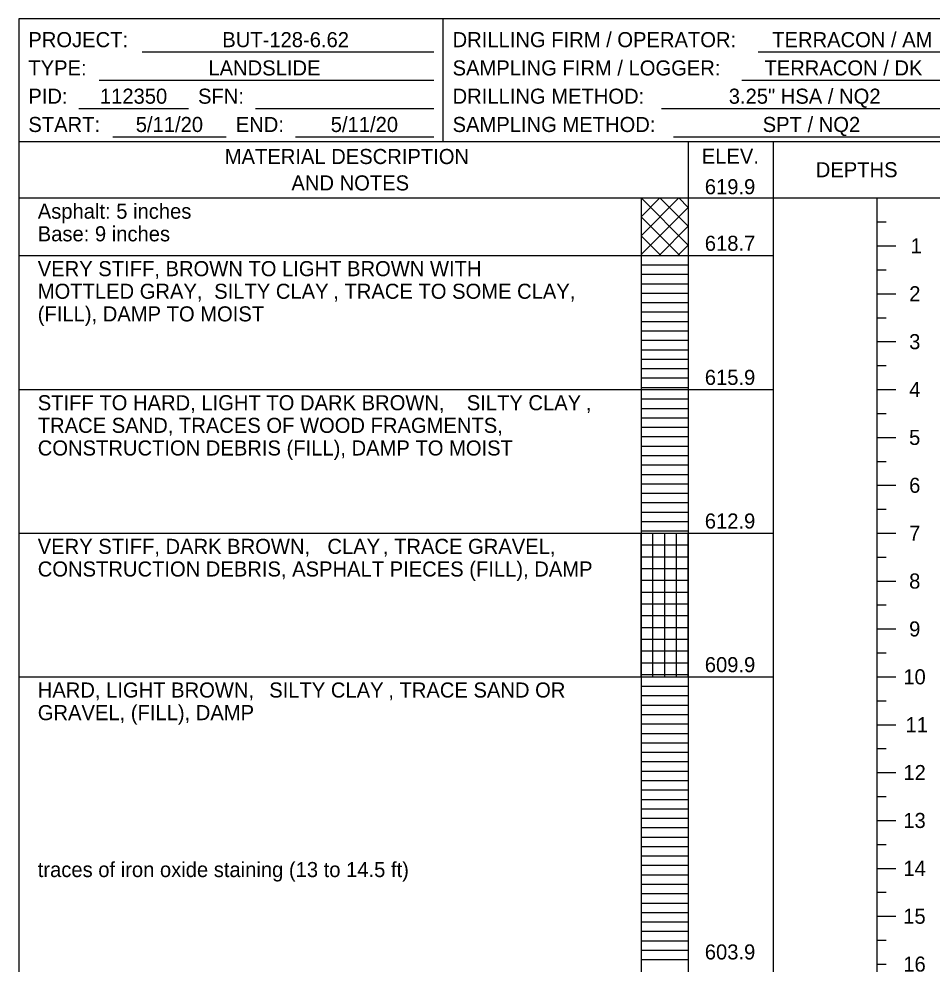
# Model space of a CAD drawing. Extents: x 0 to 0.833, y -0.32 to 0.608.
# Drawn here: x 0 to 0.4036, y 0.1905 to 0.6083 of the extents above; entities that cross this region are included whole.
import ezdxf

# ---------------------------------------------------------------- set-up
doc = ezdxf.new("R2010")
doc.units = 0

msp = doc.modelspace()

# ---------------------------------------------------------------- linework, layer by layer
msp.add_lwpolyline([(0, -0.32004), (0.83333, -0.32004), (0.83333, 0.60833), (0, 0.60833)], close=True)
for points in [[(0.1875, 0.55417), (0.1875, 0.60833)], [(0.05444, 0.59375), (0.18333, 0.59375)], [(0.32667, 0.59375), (0.4125, 0.59375)], [(0.03542, 0.58125), (0.18333, 0.58125)], [(0.31944, 0.58125), (0.4125, 0.58125)], [(0.02653, 0.56875), (0.075, 0.56875)], [(0.10458, 0.56875), (0.18333, 0.56875)], [(0.28403, 0.56875), (0.4125, 0.56875)], [(0.04153, 0.55625), (0.09167, 0.55625)], [(0.12222, 0.55625), (0.18333, 0.55625)], [(0.2893, 0.55625), (0.4125, 0.55625)], [(0, 0.55417), (0.83333, 0.55417)], [(0, 0.55417), (0.83333, 0.55417)], [(0, 0.55417), (0.83333, 0.55417)], [(0, 0.55417), (0.83333, 0.55417)], [(0, 0.55417), (0.83333, 0.55417)], [(0.29583, 0.55417), (0.29583, -0.27517)], [(0.29583, 0.55417), (0.29583, -0.27517)], [(0.33333, 0.55417), (0.33333, -0.27517)], [(0.33333, 0.55417), (0.33333, -0.27517)], [(0, 0.52917), (0.83333, 0.52917)], [(0, 0.52917), (0.83333, 0.52917)], [(0, 0.52917), (0.83333, 0.52917)], [(0, 0.52917), (0.83333, 0.52917)], [(0, 0.52917), (0.83333, 0.52917)], [(0.275, 0.52917), (0.29583, 0.50833)], [(0.275, 0.52083), (0.28333, 0.52917)], [(0.275, 0.5125), (0.29167, 0.52917)], [(0.275, 0.52917), (0.275, 0.50377)], [(0.275, 0.52917), (0.275, -0.27517)], [(0.28333, 0.52917), (0.29583, 0.51667)], [(0.29167, 0.52917), (0.29583, 0.525)], [(0.29583, 0.52917), (0.33333, 0.52917)], [(0.37917, 0.52917), (0.37917, -0.27517)], [(0.275, 0.50417), (0.29583, 0.525)], [(0.275, 0.52083), (0.29207, 0.50377)], [(0.37917, 0.51858), (0.38333, 0.51858)], [(0.28293, 0.50377), (0.29583, 0.51667)], [(0.275, 0.5125), (0.28373, 0.50377)], [(0.29127, 0.50377), (0.29583, 0.50833)], [(0.37917, 0.508), (0.3875, 0.508)], [(0.37917, 0.508), (0.38333, 0.508)], [(0, 0.50377), (0.275, 0.50377)], [(0.275, 0.50417), (0.2754, 0.50377)], [(0.275, 0.50377), (0.29583, 0.50377)], [(0.275, 0.50377), (0.29583, 0.50377)], [(0.275, 0.50377), (0.275, 0.4445)], [(0.29583, 0.50377), (0.33333, 0.50377)], [(0.275, 0.4996), (0.29583, 0.4996)], [(0.37917, 0.49742), (0.38333, 0.49742)], [(0.275, 0.49543), (0.29583, 0.49543)], [(0.275, 0.49127), (0.29583, 0.49127)], [(0.275, 0.4871), (0.29583, 0.4871)], [(0.37917, 0.48683), (0.3875, 0.48683)], [(0.37917, 0.48683), (0.38333, 0.48683)], [(0.275, 0.48293), (0.29583, 0.48293)], [(0.275, 0.47877), (0.29583, 0.47877)], [(0.275, 0.4746), (0.29583, 0.4746)], [(0.37917, 0.47625), (0.38333, 0.47625)], [(0.275, 0.47043), (0.29583, 0.47043)], [(0.275, 0.46627), (0.29583, 0.46627)], [(0.37917, 0.46567), (0.3875, 0.46567)], [(0.37917, 0.46567), (0.38333, 0.46567)], [(0.275, 0.4621), (0.29583, 0.4621)], [(0.275, 0.45793), (0.29583, 0.45793)], [(0.275, 0.45377), (0.29583, 0.45377)], [(0.37917, 0.45508), (0.38333, 0.45508)], [(0.275, 0.4496), (0.29583, 0.4496)], [(0, 0.4445), (0.275, 0.4445)], [(0.275, 0.44543), (0.29583, 0.44543)], [(0.275, 0.4445), (0.29583, 0.4445)], [(0.275, 0.4445), (0.29583, 0.4445)], [(0.275, 0.4445), (0.275, 0.381)], [(0.29583, 0.4445), (0.33333, 0.4445)], [(0.37917, 0.4445), (0.3875, 0.4445)], [(0.37917, 0.4445), (0.38333, 0.4445)], [(0.275, 0.44033), (0.29583, 0.44033)], [(0.275, 0.43617), (0.29583, 0.43617)], [(0.275, 0.432), (0.29583, 0.432)], [(0.37917, 0.43392), (0.38333, 0.43392)], [(0.275, 0.42783), (0.29583, 0.42783)], [(0.275, 0.42367), (0.29583, 0.42367)], [(0.37917, 0.42333), (0.3875, 0.42333)], [(0.37917, 0.42333), (0.38333, 0.42333)], [(0.275, 0.4195), (0.29583, 0.4195)], [(0.275, 0.41533), (0.29583, 0.41533)], [(0.275, 0.41117), (0.29583, 0.41117)], [(0.37917, 0.41275), (0.38333, 0.41275)], [(0.275, 0.407), (0.29583, 0.407)], [(0.275, 0.40283), (0.29583, 0.40283)], [(0.37917, 0.40217), (0.3875, 0.40217)], [(0.37917, 0.40217), (0.38333, 0.40217)], [(0.275, 0.39867), (0.29583, 0.39867)], [(0.275, 0.3945), (0.29583, 0.3945)], [(0.275, 0.39033), (0.29583, 0.39033)], [(0.37917, 0.39158), (0.38333, 0.39158)], [(0.275, 0.38617), (0.29583, 0.38617)], [(0, 0.381), (0.275, 0.381)], [(0.275, 0.382), (0.29583, 0.382)], [(0.275, 0.381), (0.29583, 0.381)], [(0.275, 0.381), (0.29583, 0.381)], [(0.275, 0.3175), (0.275, 0.381)], [(0.275, 0.381), (0.275, 0.3175)], [(0.28021, 0.3175), (0.28021, 0.381)], [(0.28542, 0.3175), (0.28542, 0.381)], [(0.29062, 0.3175), (0.29062, 0.381)], [(0.29583, 0.3175), (0.29583, 0.381)], [(0.29583, 0.381), (0.33333, 0.381)], [(0.37917, 0.381), (0.3875, 0.381)], [(0.37917, 0.381), (0.38333, 0.381)], [(0.275, 0.37579), (0.29583, 0.37579)], [(0.275, 0.37058), (0.29583, 0.37058)], [(0.37917, 0.37042), (0.38333, 0.37042)], [(0.275, 0.36537), (0.29583, 0.36537)], [(0.275, 0.36017), (0.29583, 0.36017)], [(0.37917, 0.35983), (0.3875, 0.35983)], [(0.37917, 0.35983), (0.38333, 0.35983)], [(0.275, 0.35496), (0.29583, 0.35496)], [(0.275, 0.34975), (0.29583, 0.34975)], [(0.37917, 0.34925), (0.38333, 0.34925)], [(0.275, 0.34454), (0.29583, 0.34454)], [(0.275, 0.33933), (0.29583, 0.33933)], [(0.37917, 0.33867), (0.3875, 0.33867)], [(0.37917, 0.33867), (0.38333, 0.33867)], [(0.275, 0.33412), (0.29583, 0.33412)], [(0.275, 0.32892), (0.29583, 0.32892)], [(0.37917, 0.32808), (0.38333, 0.32808)], [(0.275, 0.32371), (0.29583, 0.32371)], [(0.275, 0.3185), (0.29583, 0.3185)], [(0, 0.3175), (0.275, 0.3175)], [(0.275, 0.3175), (0.29583, 0.3175)], [(0.275, 0.3175), (0.29583, 0.3175)], [(0.275, 0.3175), (0.275, 0.1905)], [(0.29583, 0.3175), (0.33333, 0.3175)], [(0.37917, 0.3175), (0.3875, 0.3175)], [(0.37917, 0.3175), (0.38333, 0.3175)], [(0.275, 0.31333), (0.29583, 0.31333)], [(0.275, 0.30917), (0.29583, 0.30917)], [(0.37917, 0.30692), (0.38333, 0.30692)], [(0.275, 0.305), (0.29583, 0.305)], [(0.275, 0.30083), (0.29583, 0.30083)], [(0.275, 0.29667), (0.29583, 0.29667)], [(0.275, 0.2925), (0.29583, 0.2925)], [(0.37917, 0.29633), (0.3875, 0.29633)], [(0.37917, 0.29633), (0.38333, 0.29633)], [(0.275, 0.28833), (0.29583, 0.28833)], [(0.275, 0.28417), (0.29583, 0.28417)], [(0.37917, 0.28575), (0.38333, 0.28575)], [(0.275, 0.28), (0.29583, 0.28)], [(0.275, 0.27583), (0.29583, 0.27583)], [(0.275, 0.27167), (0.29583, 0.27167)], [(0.37917, 0.27517), (0.3875, 0.27517)], [(0.37917, 0.27517), (0.38333, 0.27517)], [(0.275, 0.2675), (0.29583, 0.2675)], [(0.275, 0.26333), (0.29583, 0.26333)], [(0.37917, 0.26458), (0.38333, 0.26458)], [(0.275, 0.25917), (0.29583, 0.25917)], [(0.275, 0.255), (0.29583, 0.255)], [(0.275, 0.25083), (0.29583, 0.25083)], [(0.37917, 0.254), (0.3875, 0.254)], [(0.37917, 0.254), (0.38333, 0.254)], [(0.275, 0.24667), (0.29583, 0.24667)], [(0.275, 0.2425), (0.29583, 0.2425)], [(0.37917, 0.24342), (0.38333, 0.24342)], [(0.275, 0.23833), (0.29583, 0.23833)], [(0.275, 0.23417), (0.29583, 0.23417)], [(0.275, 0.23), (0.29583, 0.23)], [(0.37917, 0.23283), (0.3875, 0.23283)], [(0.37917, 0.23283), (0.38333, 0.23283)], [(0.275, 0.22583), (0.29583, 0.22583)], [(0.275, 0.22167), (0.29583, 0.22167)], [(0.37917, 0.22225), (0.38333, 0.22225)], [(0.275, 0.2175), (0.29583, 0.2175)], [(0.275, 0.21333), (0.29583, 0.21333)], [(0.275, 0.20917), (0.29583, 0.20917)], [(0.37917, 0.21167), (0.3875, 0.21167)], [(0.37917, 0.21167), (0.38333, 0.21167)], [(0.275, 0.205), (0.29583, 0.205)], [(0.275, 0.20083), (0.29583, 0.20083)], [(0.37917, 0.20108), (0.38333, 0.20108)], [(0.275, 0.19667), (0.29583, 0.19667)], [(0.275, 0.1925), (0.29583, 0.1925)], [(0.37917, 0.1905), (0.38333, 0.1905)]]:
    msp.add_lwpolyline(points)

# ---------------------------------------------------------------- texts
for s, height, p in [('PROJECT:', 0.006667, (0.00417, 0.59583)), ('BUT-128-6.62', 0.0066667, (0.08989, 0.59583)), ('DRILLING FIRM / OPERATOR:', 0.0066667, (0.19167, 0.59583)), ('TERRACON / AM', 0.0066667, (0.33293, 0.59583)), ('TYPE:', 0.006667, (0.00417, 0.58333)), ('LANDSLIDE', 0.006667, (0.08374, 0.58333)), ('SAMPLING FIRM / LOGGER:', 0.0066667, (0.19167, 0.58333)), ('TERRACON / DK', 0.0066667, (0.32949, 0.58333)), ('PID:', 0.006667, (0.00417, 0.57083)), ('112350', 0.006667, (0.0358, 0.57083)), ('SFN:', 0.006667, (0.07917, 0.57083)), ('DRILLING METHOD:', 0.0066667, (0.19167, 0.57083)), ('3.25" HSA / NQ2', 0.0066667, (0.31373, 0.57083)), ('START:', 0.006667, (0.00417, 0.55833)), ('5/11/20', 0.006667, (0.05164, 0.55833)), ('END:', 0.006667, (0.09583, 0.55833)), ('5/11/20', 0.006667, (0.13782, 0.55833)), ('SAMPLING METHOD:', 0.0066667, (0.19167, 0.55833)), ('SPT / NQ2', 0.006667, (0.32872, 0.55833)), ('MATERIAL DESCRIPTION', 0.0066667, (0.09097, 0.54417)), ('ELEV.', 0.006667, (0.30179, 0.54437)), ('DEPTHS', 0.006667, (0.35218, 0.53833)), ('AND NOTES', 0.006667, (0.12044, 0.5325)), ('619.9', 0.006667, (0.30314, 0.53083)), ('Asphalt: 5 inches', 0.0066667, (0.00833, 0.52)), ('Base: 9 inches', 0.0066667, (0.00833, 0.51)), ('618.7', 0.006667, (0.30314, 0.50581)), ('1', 0.00667, (0.3941, 0.50467)), ('VERY STIFF, BROWN TO LIGHT BROWN WITH', 0.0066667, (0.00833, 0.4946)), ('MOTTLED GRAY, ', 0.0066667, (0.00833, 0.4846)), ('SILTY CLAY', 0.006667, (0.08631, 0.4846)), (', TRACE TO SOME CLAY,', 0.0066667, (0.13894, 0.4846)), ('2', 0.00667, (0.39349, 0.4835)), ('(FILL), DAMP TO MOIST', 0.0066667, (0.00833, 0.4746)), ('3', 0.00667, (0.39345, 0.46233)), ('615.9', 0.006667, (0.30314, 0.44654)), ('4', 0.00667, (0.39347, 0.44117)), ('STIFF TO HARD, LIGHT TO DARK BROWN, ', 0.0066667, (0.00833, 0.43533)), ('SILTY CLAY', 0.006667, (0.19794, 0.43533)), (',', 0.00667, (0.25057, 0.43533)), ('TRACE SAND, TRACES OF WOOD FRAGMENTS,', 0.0066667, (0.00833, 0.42533)), ('5', 0.00667, (0.39343, 0.42)), ('CONSTRUCTION DEBRIS (FILL), DAMP TO MOIST', 0.0066667, (0.00833, 0.41533)), ('6', 0.00667, (0.39345, 0.39883)), ('612.9', 0.006667, (0.30314, 0.38304)), ('7', 0.00667, (0.39345, 0.37767)), ('VERY STIFF, DARK BROWN, ', 0.0066667, (0.00833, 0.37183)), ('CLAY', 0.006667, (0.13635, 0.37183)), (', TRACE GRAVEL,', 0.0066667, (0.16086, 0.37183)), ('CONSTRUCTION DEBRIS, ASPHALT PIECES (FILL), DAMP', 0.0066667, (0.00833, 0.36183)), ('8', 0.00667, (0.39345, 0.3565)), ('9', 0.00667, (0.39345, 0.33533)), ('609.9', 0.006667, (0.30314, 0.31954)), ('10', 0.006667, (0.39088, 0.31417)), ('HARD, LIGHT BROWN, ', 0.0066667, (0.00833, 0.30833)), ('SILTY CLAY', 0.006667, (0.11063, 0.30833)), (', TRACE SAND OR', 0.0066667, (0.16326, 0.30833)), ('GRAVEL, (FILL), DAMP', 0.0066667, (0.00833, 0.29833)), ('11', 0.006667, (0.39186, 0.293)), ('12', 0.006667, (0.3909, 0.27183)), ('13', 0.006667, (0.39087, 0.25067)), ('traces of iron oxide staining (13 to 14.5 ft)', 0.0066667, (0.00833, 0.22896)), ('14', 0.006667, (0.39088, 0.2295)), ('15', 0.006667, (0.39084, 0.20833)), ('603.9', 0.006667, (0.30314, 0.19254)), ('16', 0.006667, (0.39087, 0.18717))]:
    msp.add_text(s, height=height).set_placement(p)

doc.saveas('drawing.dxf')
